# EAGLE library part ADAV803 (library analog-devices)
Audio Codec for Recordable DVD Auto generated by make-symbol-device-package-bsdl.ulp Rev. 33 Source: http://www.analog.com/static/imported-files/data_sheets/ADAV803.pdf
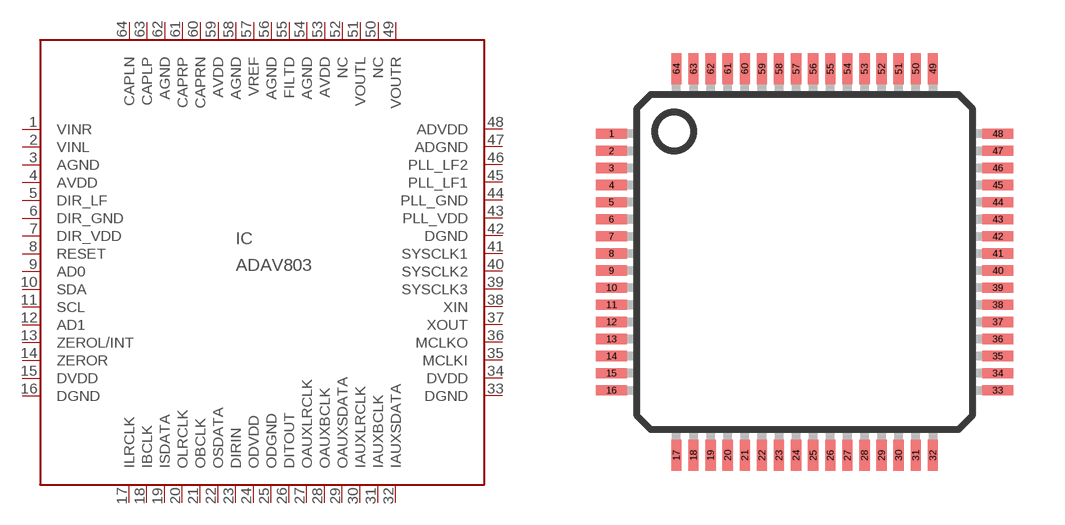
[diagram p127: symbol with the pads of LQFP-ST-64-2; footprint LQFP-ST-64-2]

Designator prefix IC

## ADAV803 (MF: ALTERA CORPORATION; MPN: ADAV803ASTZ-REEL; OC_FARNELL: unknown; OC_NEWARK: 59K0877)  [LQFP-ST-64-2]
1  VINR  in
2  VINL  in
3  AGND  pwr
4  AVDD  pwr
5  DIR_LF  in
6  DIR_GND  in
7  DIR_VDD  in
8  RESET  in
9  AD0  in
10  SDA
11  SCL  in
12  AD1  in
13  ZEROL/INT  out
14  ZEROR  out
15  DVDD  pwr
16  DGND  pwr
17  ILRCLK
18  IBCLK
19  ISDATA  in
20  OLRCLK
21  OBCLK
22  OSDATA  out
23  DIRIN  in
24  ODVDD  pwr
25  ODGND  pwr
26  DITOUT  out
27  OAUXLRCLK
28  OAUXBCLK
29  OAUXSDATA  out
30  IAUXLRCLK
31  IAUXBCLK
32  IAUXSDATA  in
33  DGND  pwr
34  DVDD  pwr
35  MCLKI  in
36  MCLKO  out
37  XOUT  in
38  XIN  in
39  SYSCLK3  out
40  SYSCLK2  out
41  SYSCLK1  out
42  DGND  pwr
43  PLL_VDD  in
44  PLL_GND  in
45  PLL_LF1  in
46  PLL_LF2  in
47  ADGND  pwr
48  ADVDD  pwr
49  VOUTR  out
50  NC  nc
51  VOUTL  out
52  NC  nc
53  AVDD  pwr
54  AGND  pwr
55  FILTD  in
56  AGND  pwr
57  VREF  in
58  AGND  pwr
59  AVDD  pwr
60  CAPRN  in
61  CAPRP  in
62  AGND  pwr
63  CAPLP  in
64  CAPLN  in

## Footprint LQFP-ST-64-2 (pad centres in mm)
64-Lead Low Profile Quad Flat Package [LQFP] (ST-64-2) COMPLIANT TO JEDEC STANDARDS MS-026-BCD Source: http://www.analog.com/UploadedFiles/Data_Sheets/288945048AD7C7019_20_1_2_4_5_6_7_0.pdf
smd 0.9 x 0.3: 1 -5.65,3.75; 2 -5.65,3.25; 3 -5.65,2.75; 4 -5.65,2.25; 5 -5.65,1.75; 6 -5.65,1.25; 7 -5.65,0.75; 8 -5.65,0.25; 9 -5.65,-0.25; 10 -5.65,-0.75; 11 -5.65,-1.25; 12 -5.65,-1.75; 13 -5.65,-2.25; 14 -5.65,-2.75; 15 -5.65,-3.25; 16 -5.65,-3.75; 33 5.65,-3.75; 34 5.65,-3.25; 35 5.65,-2.75; 36 5.65,-2.25; 37 5.65,-1.75; 38 5.65,-1.25; 39 5.65,-0.75; 40 5.65,-0.25; 41 5.65,0.25; 42 5.65,0.75; 43 5.65,1.25; 44 5.65,1.75; 45 5.65,2.25; 46 5.65,2.75; 47 5.65,3.25; 48 5.65,3.75
smd 0.3 x 0.9: 17 -3.75,-5.65; 18 -3.25,-5.65; 19 -2.75,-5.65; 20 -2.25,-5.65; 21 -1.75,-5.65; 22 -1.25,-5.65; 23 -0.75,-5.65; 24 -0.25,-5.65; 25 0.25,-5.65; 26 0.75,-5.65; 27 1.25,-5.65; 28 1.75,-5.65; 29 2.25,-5.65; 30 2.75,-5.65; 31 3.25,-5.65; 32 3.75,-5.65; 49 3.75,5.65; 50 3.25,5.65; 51 2.75,5.65; 52 2.25,5.65; 53 1.75,5.65; 54 1.25,5.65; 55 0.75,5.65; 56 0.25,5.65; 57 -0.25,5.65; 58 -0.75,5.65; 59 -1.25,5.65; 60 -1.75,5.65; 61 -2.25,5.65; 62 -2.75,5.65; 63 -3.25,5.65; 64 -3.75,5.65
